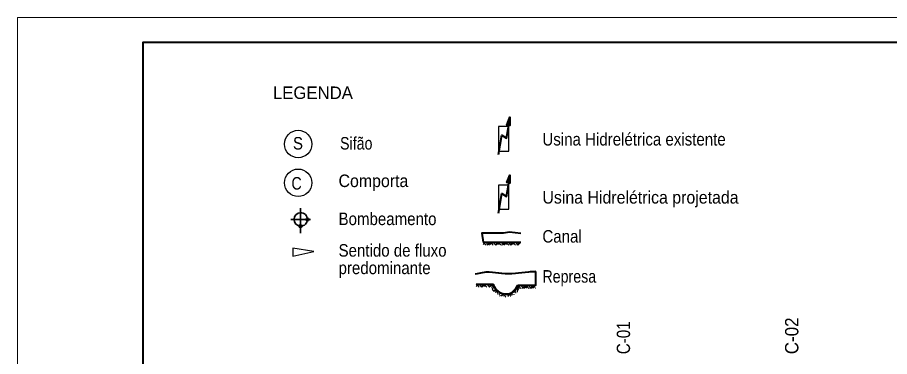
# Model space of a CAD drawing. Extents: x 8426.2 to 8495.4, y 19933.5 to 19963.2.
# Drawn here: x 8426.17 to 8443.58, y 19956.47 to 19963.25 of the extents above; entities that cross this region are included whole.
import ezdxf

# ---------------------------------------------------------------- set-up
doc = ezdxf.new("R2010")
doc.units = 0
doc.header["$LTSCALE"] = 0.11
doc.header["$PDMODE"] = 32
doc.header["$PDSIZE"] = 0.055
for name, color, linetype, lineweight in [('1', 7, 'Continuous', 35), ('2', 7, 'Continuous', 13), ('3', 7, 'Continuous', 25)]:
    doc.layers.add(name, color=color, linetype=linetype, lineweight=lineweight)

msp = doc.modelspace()

# ---------------------------------------------------------------- linework, layer by layer
at = {"layer": '1'}
for p, q in [((8431.82, 19958.94), (8431.82, 19959.44)), ((8431.63, 19959.21), (8432.02, 19959.21))]:
    msp.add_line(p, q, dxfattribs=at)
at = {"layer": '1', "lineweight": 40}
for p, q in [((8435.47, 19958.76), (8436.22, 19958.76)), ((8435.47, 19958.76), (8436.22, 19958.76)), ((8435.33, 19957.92), (8435.66, 19957.92)), ((8435.33, 19957.92), (8435.66, 19957.92)), ((8435.77, 19957.78), (8435.72, 19957.78))]:
    msp.add_line(p, q, dxfattribs=at)
at = {"layer": '1', "lineweight": 13}
for p, q in [((8435.49, 19958.76), (8435.47, 19958.74)), ((8435.53, 19958.76), (8435.47, 19958.71)), ((8435.49, 19958.73), (8435.53, 19958.7)), ((8435.52, 19958.76), (8435.56, 19958.71)), ((8435.61, 19958.76), (8435.55, 19958.7)), ((8435.56, 19958.76), (8435.59, 19958.74)), ((8435.61, 19958.74), (8435.58, 19958.7)), ((8435.65, 19958.76), (8435.61, 19958.74)), ((8435.67, 19958.76), (8435.61, 19958.71)), ((8435.64, 19958.73), (8435.67, 19958.7)), ((8435.66, 19958.76), (8435.71, 19958.71)), ((8435.71, 19958.76), (8435.75, 19958.74)), ((8435.77, 19958.76), (8435.71, 19958.7)), ((8435.77, 19958.74), (8435.72, 19958.7)), ((8435.79, 19958.76), (8435.77, 19958.74)), ((8435.82, 19958.76), (8435.77, 19958.71)), ((8435.78, 19958.73), (8435.83, 19958.7)), ((8435.82, 19958.76), (8435.87, 19958.71)), ((8435.92, 19958.76), (8435.84, 19958.7)), ((8435.87, 19958.76), (8435.88, 19958.74)), ((8435.92, 19958.74), (8435.88, 19958.7)), ((8435.94, 19958.76), (8435.92, 19958.74)), ((8435.96, 19958.76), (8435.92, 19958.71)), ((8435.94, 19958.73), (8435.98, 19958.7)), ((8435.96, 19958.76), (8436.01, 19958.71)), ((8436.05, 19958.76), (8436, 19958.7)), ((8436.01, 19958.76), (8436.03, 19958.74)), ((8436.05, 19958.74), (8436.02, 19958.7)), ((8436.08, 19958.76), (8436.05, 19958.74)), ((8436.11, 19958.76), (8436.05, 19958.71)), ((8436.08, 19958.73), (8436.11, 19958.7)), ((8436.11, 19958.76), (8436.15, 19958.71)), ((8436.2, 19958.76), (8436.14, 19958.7)), ((8436.16, 19958.76), (8436.17, 19958.74)), ((8436.2, 19958.74), (8436.16, 19958.7)), ((8435.36, 19957.92), (8435.33, 19957.9)), ((8435.39, 19957.92), (8435.33, 19957.87)), ((8435.36, 19957.89), (8435.39, 19957.86)), ((8435.38, 19957.92), (8435.43, 19957.87)), ((8435.48, 19957.92), (8435.42, 19957.86)), ((8435.43, 19957.92), (8435.47, 19957.9)), ((8435.48, 19957.9), (8435.44, 19957.86)), ((8435.52, 19957.92), (8435.48, 19957.9)), ((8435.54, 19957.92), (8435.48, 19957.87)), ((8435.5, 19957.89), (8435.54, 19957.86)), ((8435.54, 19957.92), (8435.59, 19957.87)), ((8435.64, 19957.92), (8435.58, 19957.86)), ((8435.59, 19957.92), (8435.61, 19957.9)), ((8435.64, 19957.9), (8435.59, 19957.86)), ((8435.69, 19957.87), (8435.61, 19957.9)), ((8435.66, 19957.92), (8435.64, 19957.9)), ((8435.69, 19957.92), (8435.64, 19957.87)), ((8435.65, 19957.89), (8435.64, 19957.84)), ((8435.67, 19957.9), (8435.65, 19957.91)), ((8435.69, 19957.88), (8435.65, 19957.81)), ((8436.2, 19957.9), (8436.16, 19957.87)), ((8436.22, 19957.9), (8436.16, 19957.84)), ((8436.16, 19957.87), (8436.22, 19957.89)), ((8436.16, 19957.88), (8436.17, 19957.8)), ((8436.18, 19957.87), (8436.22, 19957.83)), ((8436.22, 19957.89), (8436.27, 19957.84)), ((8436.32, 19957.9), (8436.24, 19957.83)), ((8436.27, 19957.9), (8436.29, 19957.87)), ((8436.32, 19957.87), (8436.28, 19957.83)), ((8436.34, 19957.9), (8436.32, 19957.87)), ((8436.37, 19957.9), (8436.32, 19957.84)), ((8436.34, 19957.87), (8436.38, 19957.83)), ((8436.37, 19957.89), (8436.41, 19957.84)), ((8436.46, 19957.9), (8436.4, 19957.83)), ((8436.41, 19957.9), (8436.44, 19957.87)), ((8436.46, 19957.87), (8436.43, 19957.83)), ((8436.49, 19957.9), (8436.46, 19957.87)), ((8436.51, 19957.9), (8436.46, 19957.84)), ((8436.49, 19957.87), (8436.51, 19957.83)), ((8435.75, 19957.8), (8435.65, 19957.8)), ((8435.72, 19957.78), (8435.67, 19957.78)), ((8435.71, 19957.83), (8435.71, 19957.8)), ((8435.78, 19957.77), (8435.71, 19957.75)), ((8435.75, 19957.76), (8435.76, 19957.71)), ((8435.78, 19957.77), (8435.79, 19957.7)), ((8435.88, 19957.72), (8435.79, 19957.68)), ((8435.83, 19957.74), (8435.84, 19957.71)), ((8435.87, 19957.71), (8435.83, 19957.68)), ((8435.89, 19957.72), (8435.87, 19957.71)), ((8435.93, 19957.72), (8435.87, 19957.68)), ((8435.89, 19957.7), (8435.92, 19957.66)), ((8435.93, 19957.72), (8435.98, 19957.68)), ((8436.02, 19957.74), (8435.96, 19957.67)), ((8435.98, 19957.72), (8436, 19957.71)), ((8436.02, 19957.72), (8436.01, 19957.67)), ((8436.04, 19957.75), (8436.02, 19957.72)), ((8436.05, 19957.77), (8436.04, 19957.69)), ((8436.05, 19957.76), (8436.12, 19957.76)), ((8436.05, 19957.72), (8436.09, 19957.71)), ((8436.1, 19957.8), (8436.12, 19957.78)), ((8436.12, 19957.83), (8436.12, 19957.74)), ((8436.15, 19957.84), (8436.16, 19957.82)), ((8436.15, 19957.81), (8436.15, 19957.76)), ((8436.16, 19957.83), (8436.22, 19957.84))]:
    msp.add_line(p, q, dxfattribs=at)
at = {"layer": '1', "lineweight": 25}
msp.add_line((8436.16, 19957.9), (8436.52, 19957.9), dxfattribs=at)
at = {"layer": '1', "lineweight": 13}
msp.add_lwpolyline([(8426.17, 19933.55), (8495.44, 19933.55), (8495.44, 19963.25), (8426.17, 19963.25)], close=True, dxfattribs=at)
at = {"layer": '1', "lineweight": 40}
for points in [[(8494.94, 19962.75), (8428.67, 19962.75), (8428.67, 19934.05)], [(8436, 19961.09), (8435.94, 19961.1), (8436, 19961.26), (8436, 19961.09), (8436, 19961.1), (8436, 19961.21), (8435.95, 19961.12), (8435.99, 19961.1), (8435.99, 19961.18), (8435.96, 19961.13), (8435.98, 19961.13), (8435.99, 19961.14)], [(8435.77, 19960.51), (8435.84, 19960.9), (8435.93, 19960.84), (8435.98, 19961.1)], [(8436.22, 19958.93), (8435.99, 19958.96), (8435.87, 19958.94), (8435.62, 19958.94), (8435.44, 19958.94), (8435.47, 19958.76)], [(8436.16, 19957.9), (8436.52, 19957.9), (8436.52, 19958.17)], [(8435.66, 19957.92), (8435.71, 19957.84), (8435.76, 19957.78), (8435.83, 19957.74), (8435.92, 19957.72), (8436, 19957.72), (8436.06, 19957.77), (8436.12, 19957.83), (8436.16, 19957.9)]]:
    msp.add_lwpolyline(points, dxfattribs=at)
at = {"layer": '1', "lineweight": 25}
msp.add_lwpolyline([(8435.98, 19961.07), (8435.77, 19961.07), (8435.77, 19960.58), (8435.98, 19960.58)], close=True, dxfattribs=at)
at = {"layer": '1'}
for points in [[(8431.96, 19959.21), (8431.82, 19959.21), (8431.82, 19959.35)], [(8431.69, 19959.21), (8431.82, 19959.21), (8431.82, 19959.08)], [(8435.44, 19958.94), (8435.62, 19958.94), (8435.87, 19958.94), (8435.99, 19958.96), (8436.22, 19958.93)]]:
    msp.add_lwpolyline(points, dxfattribs=at)
at = {"layer": '1', "lineweight": 25}
for centre in [(8431.773, 19960.72), (8431.773, 19959.946)]:
    msp.add_circle(centre, 0.274, dxfattribs=at)
at = {"layer": '1'}
for start, end in [(91.6917, 178.6539), (0.2399, 91.3209), (179.2101, 269.1404), (269.1404, 0.2097)]:
    msp.add_arc((8431.825, 19959.213), 0.134, start, end, dxfattribs=at)
at = {"layer": '1', "lineweight": 40}
msp.add_arc((8435.921, 19957.993), 0.268, 195.0853, 339.4479, dxfattribs=at)
at = {"layer": '1'}
msp.add_spline([(8435.31, 19958.12), (8435.59, 19958.16), (8435.84, 19958.13), (8436.11, 19958.13), (8436.37, 19958.16), (8436.52, 19958.17)], degree=3, dxfattribs=at)
at = {"layer": '1', "lineweight": 40}
msp.add_spline([(8436.52, 19958.17), (8436.37, 19958.16), (8436.11, 19958.13), (8435.84, 19958.13), (8435.59, 19958.16), (8435.31, 19958.12)], degree=3, dxfattribs=at)
at = {"layer": '1'}
for p in [(8431.82, 19959.08), (8431.96, 19959.21)]:
    msp.add_point(p, dxfattribs=at)
at = {"layer": '2', "lineweight": 25}
msp.add_lwpolyline([(8432.09, 19958.57), (8431.67, 19958.64), (8431.67, 19958.48)], close=True, dxfattribs=at)
at = {"layer": '3', "lineweight": 40}
for points in [[(8435.77, 19959.34), (8435.84, 19959.73), (8435.93, 19959.67), (8435.98, 19959.94)], [(8436, 19959.94), (8435.94, 19959.95), (8436, 19960.1), (8436, 19959.94), (8436, 19959.95), (8436, 19960.06), (8435.95, 19959.96), (8435.99, 19959.95), (8435.99, 19960.01), (8435.96, 19959.96), (8435.98, 19959.96), (8435.99, 19959.99)]]:
    msp.add_lwpolyline(points, dxfattribs=at)
at = {"layer": '3'}
msp.add_lwpolyline([(8435.98, 19959.9), (8435.77, 19959.9), (8435.77, 19959.42), (8435.98, 19959.42)], close=True, dxfattribs=at)

# ---------------------------------------------------------------- texts
at = {"layer": '1'}
msp.add_text('LEGENDA', height=0.2498, dxfattribs=at).set_placement((8431.27, 19961.62))
for s, height, width, p in [('S', 0.25, 0.9, (8431.67, 19960.61)), ('Sifão', 0.2498, 0.85, (8432.61, 19960.61)), ('Usina Hidrelétrica existente', 0.2498, 0.9, (8436.65, 19960.69)), ('C', 0.25, 0.85, (8431.64, 19959.81)), ('Comporta', 0.2498, 0.95, (8432.58, 19959.86)), ('Usina Hidrelétrica projetada', 0.2498, 0.95, (8436.65, 19959.53)), ('Bombeamento', 0.2498, 0.9, (8432.58, 19959.1)), ('Canal', 0.2498, 0.9, (8436.65, 19958.75)), ('Sentido de fluxo', 0.2498, 0.9, (8432.58, 19958.47)), ('predominante', 0.2498, 0.9, (8432.58, 19958.12)), ('Represa', 0.2498, 0.85, (8436.65, 19957.95))]:
    msp.add_text(s, height=height, dxfattribs=dict(at, width=width)).set_placement(p)
for s, width, p in [('C-01', 0.85, (8438.4, 19956.52)), ('C-02', 0.95, (8441.76, 19956.52))]:
    msp.add_text(s, height=0.2665, rotation=90, dxfattribs=dict(at, width=width)).set_placement(p)

doc.saveas('drawing.dxf')
